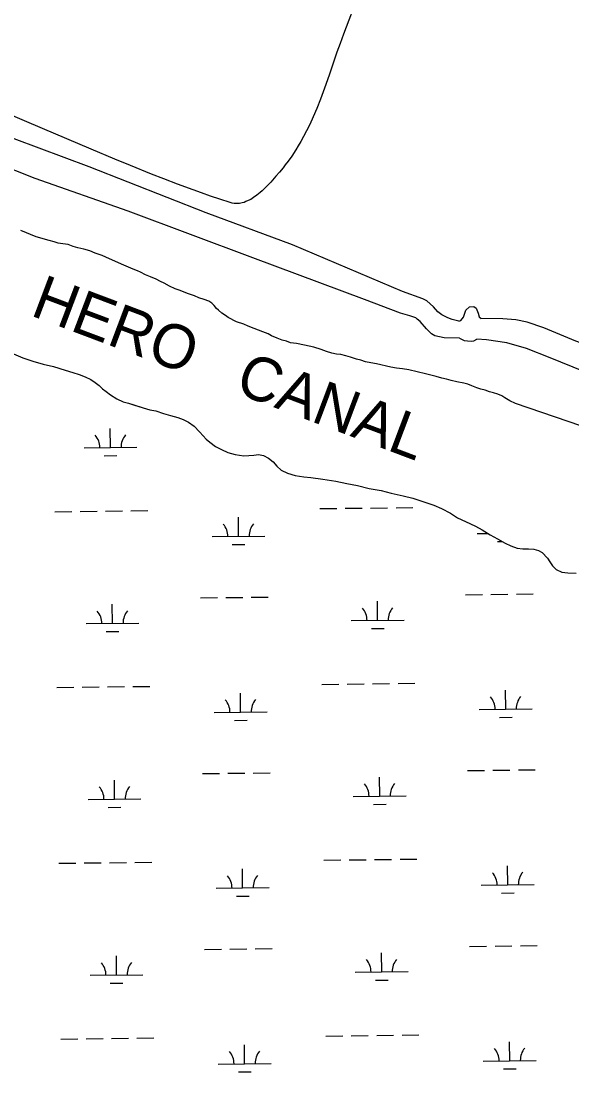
# Model space of a CAD drawing. Extents: x 3678539 to 3716648, y 451386 to 477139.
# Drawn here: x 3688062 to 3689105, y 471723 to 473712 of the extents above; entities that cross this region are included whole.
import ezdxf

# ---------------------------------------------------------------- set-up
doc = ezdxf.new("R2010")
doc.units = 0
for name, color, linetype in [('V-LEVE-TOET', 7, 'Continuous'), ('V-RIVR-IDEN', 7, 'Continuous'), ('V-SITE-VEGE', 7, 'Continuous'), ('V-TOPO-SHOR', 7, 'Continuous'), ('V-WETL-SWMP', 7, 'Continuous')]:
    doc.layers.add(name, color=color, linetype=linetype)

msp = doc.modelspace()

# ---------------------------------------------------------------- linework, layer by layer
at = {"layer": 'V-LEVE-TOET'}
for points in [[(3688890.9, 473144.2), (3688878.2, 473147.4), (3688869.9, 473150.6), (3688858.4, 473156.2), (3688851.3, 473161.8), (3688843, 473171.4), (3688830.4, 473182.9), (3688822.5, 473186.6), (3688784.5, 473200.6), (3688576, 473288.6), (3688412.5, 473349.4), (3688191.3, 473436.2), (3688049.3, 473488.9), (3687970.5, 473514.3), (3687915.5, 473532.1), (3687813.4, 473571.9), (3687684.8, 473628.5), (3687519.9, 473710.3)], [(3687525.9, 473649.2), (3687711, 473557.8), (3687877.2, 473489.1), (3687948.4, 473462.5), (3688011.3, 473445.1), (3688088.5, 473415), (3688264.2, 473352.9), (3688500.5, 473264.8), (3688711.9, 473185.6), (3688779.9, 473160.2), (3688797.7, 473154.6), (3688808.8, 473150.9)], [(3688890.9, 473144.2), (3688894.9, 473145.3), (3688899.4, 473152), (3688904.4, 473165), (3688911.1, 473171.1), (3688919.2, 473172.2), (3688923.9, 473169), (3688927.3, 473159.4), (3688929.6, 473152.1), (3688932.9, 473149.1)], [(3688892.4, 473111.7), (3688863, 473112.7), (3688845.2, 473116.3), (3688839.3, 473120.3), (3688829.4, 473129.9), (3688817.6, 473143.5), (3688811.7, 473148.2), (3688808.8, 473150.9)], [(3690363.1, 472593.4), (3689869.1, 472770.9), (3689805.8, 472791.9), (3689790, 472797.9), (3689781.7, 472803.9), (3689758.3, 472813.5), (3689712.5, 472837.2), (3689691.1, 472844.8), (3689631, 472872.9), (3689518.7, 472942.1), (3689437.7, 472988.5), (3689383.5, 473014.6), (3689375.6, 473017.8), (3689315.8, 473038.8), (3689184.4, 473080.3), (3689112.3, 473106.5), (3689051.8, 473131.8), (3689020.1, 473142.3), (3688998.7, 473146.7), (3688974.2, 473148.9), (3688932.9, 473149.1)], [(3688892.4, 473111.7), (3688901.1, 473107.9), (3688907.2, 473106.7), (3688913.9, 473106.1), (3688919.4, 473107.2), (3688924.9, 473110.4)], [(3691441, 472118), (3691128, 472240.6), (3690885.1, 472340.6), (3690681, 472415.1), (3690462.2, 472494.8), (3690237.1, 472581.2), (3690036.9, 472657.6), (3689882.5, 472713.5), (3689686.7, 472783.2), (3689628.1, 472808.5), (3689612.3, 472817.7), (3689557, 472852.5), (3689499.3, 472888.4), (3689440.1, 472925.6), (3689391, 472951.3), (3689347.9, 472971.3), (3689313.9, 472983.4), (3689191.2, 473023.3), (3689063.8, 473075.1), (3689018.7, 473092.4), (3688981.9, 473103.3), (3688943.5, 473108.7), (3688924.9, 473110.4)]]:
    msp.add_lwpolyline(points, dxfattribs=at)
at = {"layer": 'V-SITE-VEGE'}
msp.add_lwpolyline([(3688700.6, 473762), (3688672.4, 473687.4), (3688666, 473669.7), (3688660.2, 473653.2), (3688645.3, 473609.6), (3688636.8, 473585), (3688629.2, 473564.4), (3688622, 473546.4), (3688615.3, 473530.7), (3688608.8, 473516.5), (3688602.6, 473504.2), (3688596.9, 473493.4), (3688591.6, 473483.9), (3688586.7, 473475.7), (3688582.2, 473468.5), (3688574.4, 473456.7), (3688567.6, 473447.1), (3688562.2, 473439.9), (3688558.1, 473434.5), (3688551.5, 473426.4), (3688544.7, 473418.4), (3688535, 473407.4), (3688526.4, 473398.4), (3688522.4, 473394.5), (3688518.6, 473390.9), (3688515, 473387.7), (3688511.6, 473384.9), (3688508.3, 473382.3), (3688502.4, 473378.1), (3688497, 473374.7), (3688492.2, 473372.2), (3688487.9, 473370.3), (3688484.2, 473368.9), (3688480.9, 473368), (3688478.1, 473367.3), (3688475.5, 473366.9), (3688471.1, 473366.6), (3688467.8, 473366.6), (3688465.3, 473366.8), (3688461.5, 473367.5), (3688457.7, 473368.5), (3688438.5, 473374.8), (3688420.6, 473381), (3688403.7, 473386.9), (3688387.8, 473392.6), (3688358.1, 473403.6), (3688332.1, 473413.6), (3688309.3, 473422.5), (3688269.5, 473438.6), (3688239.7, 473450.9), (3688195.1, 473469.6), (3688103, 473508.8), (3687957, 473570.5)], dxfattribs=at)
at = {"layer": 'V-TOPO-SHOR'}
for points in [[(3688972.3, 473003.1), (3688964.9, 473006.1), (3688956.5, 473008.5), (3688948.8, 473010.7), (3688940.6, 473013.3), (3688932.2, 473015.8), (3688925, 473018.2), (3688915.5, 473021.7), (3688907.6, 473024.9), (3688900.5, 473027.1), (3688887, 473029.5), (3688876.4, 473031.9), (3688867.2, 473034.4), (3688858.5, 473036.5), (3688847.9, 473039.2), (3688837.9, 473041.9), (3688827.8, 473044.4), (3688796.4, 473051.9), (3688784, 473053.9), (3688773.1, 473055.2), (3688762.3, 473057.2), (3688753.9, 473058.8), (3688743.3, 473061.8), (3688734.8, 473063.7), (3688724.3, 473065.6), (3688714, 473067.5), (3688705.2, 473070.2), (3688697.3, 473072.3), (3688685.7, 473075.8), (3688676.7, 473078.5), (3688667.5, 473081.2), (3688659.3, 473082), (3688650.3, 473083.4), (3688640.3, 473086.6), (3688630.2, 473090.4), (3688616.5, 473094.7), (3688598.8, 473099), (3688583.5, 473101.8), (3688572.1, 473103.4), (3688564.7, 473106.1), (3688556.5, 473108.3), (3688546.8, 473112.3), (3688536.5, 473116.3), (3688530.1, 473120), (3688519.6, 473124.3), (3688511.9, 473127), (3688503.5, 473130), (3688492.1, 473134.8), (3688483.7, 473138.5), (3688469.7, 473143.1), (3688454.4, 473150.9), (3688449.4, 473154.6), (3688442.5, 473159.6), (3688436.2, 473164.7), (3688432.3, 473168.4), (3688427.5, 473173.7), (3688423.3, 473178.5), (3688417.8, 473182.3), (3688408.6, 473185.2), (3688398.5, 473188.5), (3688390.3, 473191.9), (3688379, 473196), (3688371.1, 473198.9), (3688363.2, 473201.9), (3688353.9, 473205.6), (3688343.1, 473210.7), (3688333.3, 473215.8), (3688326.2, 473219.3), (3688317.8, 473223.5), (3688307.2, 473228.1), (3688297.7, 473232.1), (3688288, 473237.2), (3688282.7, 473239.3), (3688274.5, 473242.5), (3688265.5, 473246.3), (3688256.8, 473250), (3688229.6, 473262.1), (3688215.7, 473268.5), (3688202.7, 473273.1), (3688192.4, 473277.1), (3688181.1, 473280.3), (3688169.7, 473283), (3688160.5, 473285.7), (3688151.2, 473289.2), (3688141.2, 473290.3), (3688132.2, 473292), (3688124.5, 473294.1), (3688115.3, 473296.8), (3688091, 473303.6), (3688061.4, 473315.6)], [(3688048.1, 473082.1), (3688065.2, 473075.1), (3688084.3, 473068.7), (3688104, 473062.8), (3688123.7, 473058.3), (3688145.5, 473051.3), (3688160.4, 473047), (3688172.2, 473043), (3688183.3, 473039), (3688194.3, 473034), (3688202.7, 473028.1), (3688209.7, 473022.3), (3688216.5, 473016.2), (3688223.1, 473010.9), (3688231.7, 473004.8), (3688243.5, 472996.9), (3688255.6, 472991.8), (3688265.5, 472988.9), (3688275.3, 472985.9), (3688293.4, 472980.1), (3688306, 472976.6), (3688317, 472974.4), (3688331.9, 472969.3)], [(3689247.6, 472903), (3688997.9, 472988.4), (3688987.1, 472993.3), (3688978.1, 472999.4), (3688972.3, 473003.1)], [(3688331.9, 472969.3), (3688344.8, 472965.9), (3688358.7, 472962.1), (3688369.2, 472958.1), (3688379.4, 472953), (3688389.9, 472945.4), (3688400.1, 472934.8), (3688406.6, 472927.4), (3688412.4, 472921.1), (3688419.7, 472915), (3688429.9, 472907.3), (3688441.5, 472901.2), (3688453.5, 472895.9), (3688467.2, 472891.6), (3688484, 472889.4), (3688502.7, 472890.9), (3688511.6, 472891.9), (3688521.3, 472890), (3688530.8, 472885.2), (3688539.1, 472878.3), (3688546.5, 472870.1), (3688554.6, 472862.5), (3688566.4, 472856.4), (3688581.1, 472852.3), (3688597.6, 472849.9), (3688610.7, 472848.5), (3688633.6, 472845.5), (3688658, 472841.4), (3688678.8, 472837.1), (3688698.7, 472833.3), (3688720.8, 472827.7), (3688743.9, 472823.6), (3688762.5, 472818.8), (3688785.4, 472813.9), (3688804, 472809.1), (3688843.4, 472796.2), (3688858.3, 472789.8), (3688874.8, 472781), (3688888.5, 472772.3), (3688903.7, 472765.1), (3688922.3, 472756.1), (3688934.9, 472749.4), (3688950.1, 472740.1), (3688964, 472732.5), (3688978.4, 472724.2), (3688989.1, 472718.9), (3689001.2, 472714.9), (3689012.2, 472713.5), (3689022.5, 472713.5), (3689032.7, 472712.9), (3689041.9, 472710.5), (3689048.7, 472706.2), (3689058.4, 472695.7), (3689062.8, 472688.5), (3689068.3, 472681.4), (3689075.4, 472674.3), (3689085.9, 472669.5), (3689097.2, 472667.9), (3689112.9, 472667.5)]]:
    msp.add_lwpolyline(points, dxfattribs=at)
at = {"layer": 'V-WETL-SWMP'}
for p, q in [((3688048.1, 473082.1), (3688065.2, 473075.1)), ((3688065.2, 473075.1), (3688084.3, 473068.7)), ((3688084.3, 473068.7), (3688104, 473062.8)), ((3688104, 473062.8), (3688123.7, 473058.3)), ((3688123.7, 473058.3), (3688145.5, 473051.3)), ((3688145.5, 473051.3), (3688160.4, 473047)), ((3688160.4, 473047), (3688172.2, 473043)), ((3688172.2, 473043), (3688183.3, 473039)), ((3688183.3, 473039), (3688194.3, 473034)), ((3688194.3, 473034), (3688202.7, 473028.1)), ((3688202.7, 473028.1), (3688209.7, 473022.3)), ((3688209.7, 473022.3), (3688216.5, 473016.2)), ((3688216.5, 473016.2), (3688223.1, 473010.9)), ((3688223.1, 473010.9), (3688231.7, 473004.8)), ((3688231.7, 473004.8), (3688243.5, 472996.9)), ((3688243.5, 472996.9), (3688255.6, 472991.8)), ((3688255.6, 472991.8), (3688265.5, 472988.9)), ((3688265.5, 472988.9), (3688275.2, 472985.9)), ((3688275.2, 472985.9), (3688293.4, 472980.1)), ((3688293.4, 472980.1), (3688306, 472976.6)), ((3688306, 472976.6), (3688317, 472974.4)), ((3688317, 472974.4), (3688331.9, 472969.3)), ((3688331.9, 472969.3), (3688344.8, 472965.9)), ((3688344.8, 472965.9), (3688358.7, 472962.1)), ((3688358.7, 472962.1), (3688369.2, 472958.1)), ((3688369.2, 472958.1), (3688379.4, 472953)), ((3688379.4, 472953), (3688389.9, 472945.4)), ((3688389.9, 472945.4), (3688400.1, 472934.8)), ((3688231.5, 472905), (3688231, 472941)), ((3688400.1, 472934.8), (3688406.6, 472927.4)), ((3688406.6, 472927.4), (3688412.4, 472921.1)), ((3688181.5, 472904.5), (3688281.4, 472905.6)), ((3688412.4, 472921.1), (3688419.7, 472915)), ((3688419.7, 472915), (3688429.9, 472907.3)), ((3688429.9, 472907.3), (3688441.5, 472901.2)), ((3688219.6, 472889.5), (3688243.6, 472889.7)), ((3688441.5, 472901.2), (3688453.5, 472895.9)), ((3688453.5, 472895.9), (3688467.2, 472891.6)), ((3688467.2, 472891.6), (3688484, 472889.4)), ((3688484, 472889.4), (3688502.7, 472890.9)), ((3688502.7, 472890.9), (3688511.6, 472891.9)), ((3688511.6, 472891.9), (3688521.3, 472890)), ((3688521.3, 472890), (3688530.8, 472885.2)), ((3688530.8, 472885.2), (3688539.1, 472878.3)), ((3688539.1, 472878.3), (3688546.4, 472870.1)), ((3688546.4, 472870.1), (3688554.6, 472862.5)), ((3688554.6, 472862.5), (3688566.4, 472856.4)), ((3688566.4, 472856.4), (3688581.1, 472852.3)), ((3688581.1, 472852.3), (3688597.6, 472849.9)), ((3688597.6, 472849.9), (3688610.7, 472848.5)), ((3688610.7, 472848.5), (3688633.6, 472845.5)), ((3688633.6, 472845.5), (3688658, 472841.4)), ((3688658, 472841.4), (3688678.8, 472837.1)), ((3688678.8, 472837.1), (3688698.7, 472833.3)), ((3688698.7, 472833.3), (3688720.8, 472827.7)), ((3688720.8, 472827.7), (3688743.9, 472823.6)), ((3688743.9, 472823.6), (3688762.5, 472818.8)), ((3688762.5, 472818.8), (3688785.4, 472813.9)), ((3688785.4, 472813.9), (3688804, 472809.1)), ((3688804, 472809.1), (3688843.4, 472796.2)), ((3688222, 472784.8), (3688254, 472785.2)), ((3688270, 472785.4), (3688302, 472785.8)), ((3688627.9, 472789.5), (3688659.9, 472789.9)), ((3688675.9, 472790.1), (3688707.9, 472790.4)), ((3688723.9, 472790.6), (3688755.9, 472791)), ((3688771.9, 472791.2), (3688803.9, 472791.5)), ((3688843.4, 472796.2), (3688858.3, 472789.8)), ((3688858.3, 472789.8), (3688874.8, 472781)), ((3688126, 472783.7), (3688158, 472784.1)), ((3688174, 472784.3), (3688206, 472784.7)), ((3688473.9, 472737), (3688473.5, 472773)), ((3688874.8, 472781), (3688888.5, 472772.3)), ((3688888.5, 472772.3), (3688903.7, 472765.1)), ((3688903.7, 472765.1), (3688922.3, 472756.1)), ((3688922.3, 472756.1), (3688934.9, 472749.4)), ((3688934.9, 472749.4), (3688950.1, 472740.1)), ((3688423.9, 472736.4), (3688523.9, 472737.6)), ((3688925.7, 472742.2), (3688946.4, 472742.4)), ((3688950.1, 472740.1), (3688964, 472732.5)), ((3688963.9, 472727.2), (3688973, 472727.3)), ((3688964, 472732.5), (3688978.4, 472724.2)), ((3688462, 472721.4), (3688486, 472721.7)), ((3688978.4, 472724.2), (3688989.1, 472718.9)), ((3688989.1, 472718.9), (3689001.2, 472714.9)), ((3689001.2, 472714.9), (3689012.2, 472713.5)), ((3689012.2, 472713.5), (3689022.5, 472713.5)), ((3689022.5, 472713.5), (3689032.7, 472712.9)), ((3689032.7, 472712.9), (3689041.9, 472710.5)), ((3689041.9, 472710.5), (3689048.7, 472706.2)), ((3689048.7, 472706.2), (3689058.4, 472695.7)), ((3689058.4, 472695.7), (3689062.8, 472688.5)), ((3689062.8, 472688.5), (3689068.3, 472681.4)), ((3689068.3, 472681.4), (3689075.4, 472674.3)), ((3689075.4, 472674.3), (3689085.9, 472669.5)), ((3689085.9, 472669.5), (3689097.2, 472667.9)), ((3689097.2, 472667.9), (3689112.9, 472667.5)), ((3688903.7, 472626.5), (3688935.7, 472626.9)), ((3688951.7, 472627), (3688983.7, 472627.4)), ((3688999.7, 472627.6), (3689031.7, 472628)), ((3688235.3, 472572.4), (3688234.9, 472608.4)), ((3688401.8, 472620.7), (3688433.8, 472621.1)), ((3688449.8, 472621.3), (3688481.8, 472621.6)), ((3688497.8, 472621.8), (3688529.8, 472622.2)), ((3688737.1, 472578.1), (3688736.7, 472614.1)), ((3688185.3, 472571.8), (3688285.3, 472572.9)), ((3688687.2, 472577.6), (3688787.1, 472578.7)), ((3688223.5, 472556.8), (3688247.5, 472557.1)), ((3688725.3, 472562.6), (3688749.3, 472562.8)), ((3688129.8, 472451.1), (3688161.8, 472451.4)), ((3688177.8, 472451.6), (3688209.8, 472452)), ((3688225.8, 472452.2), (3688257.8, 472452.6)), ((3688273.8, 472452.7), (3688305.8, 472453.1)), ((3688631.7, 472456.8), (3688663.7, 472457.2)), ((3688679.7, 472457.4), (3688711.7, 472457.8)), ((3688727.7, 472458), (3688759.7, 472458.3)), ((3688775.7, 472458.5), (3688807.7, 472458.9)), ((3688477.7, 472404.3), (3688477.3, 472440.3)), ((3688979.6, 472410.1), (3688979.2, 472446.1)), ((3688929.6, 472409.5), (3689029.6, 472410.7)), ((3688427.7, 472403.8), (3688527.7, 472404.9)), ((3688465.9, 472388.8), (3688489.9, 472389)), ((3688967.7, 472394.5), (3688991.7, 472394.8)), ((3688405.6, 472288.1), (3688437.6, 472288.4)), ((3688453.6, 472288.6), (3688485.6, 472289)), ((3688501.6, 472289.2), (3688533.6, 472289.5)), ((3688907.5, 472293.8), (3688939.5, 472294.2)), ((3688955.5, 472294.4), (3688987.5, 472294.8)), ((3689003.5, 472294.9), (3689035.5, 472295.3)), ((3688239.1, 472239.7), (3688238.7, 472275.7)), ((3688741, 472245.5), (3688740.6, 472281.5)), ((3688189.1, 472239.1), (3688289.1, 472240.3)), ((3688691, 472244.9), (3688791, 472246.1)), ((3688729.1, 472229.9), (3688753.1, 472230.2)), ((3688227.3, 472224.2), (3688251.3, 472224.4)), ((3688133.6, 472118.4), (3688165.6, 472118.8)), ((3688181.6, 472119), (3688213.6, 472119.3)), ((3688229.6, 472119.5), (3688261.6, 472119.9)), ((3688277.6, 472120.1), (3688309.6, 472120.5)), ((3688635.5, 472124.2), (3688667.5, 472124.6)), ((3688683.5, 472124.7), (3688715.5, 472125.1)), ((3688731.5, 472125.3), (3688763.5, 472125.7)), ((3688779.5, 472125.9), (3688811.5, 472126.2)), ((3688983.4, 472077.4), (3688983, 472113.4)), ((3688481.5, 472071.7), (3688481.1, 472107.7)), ((3688431.5, 472071.1), (3688531.5, 472072.3)), ((3688933.4, 472076.9), (3689033.4, 472078)), ((3688469.7, 472056.1), (3688493.7, 472056.4)), ((3688971.6, 472061.9), (3688995.6, 472062.2)), ((3688409.4, 471955.4), (3688441.4, 471955.8)), ((3688457.4, 471956), (3688489.4, 471956.3)), ((3688505.4, 471956.5), (3688537.4, 471956.9)), ((3688911.3, 471961.2), (3688943.3, 471961.5)), ((3688959.3, 471961.7), (3688991.3, 471962.1)), ((3689007.3, 471962.3), (3689039.3, 471962.7)), ((3688242.9, 471907.1), (3688242.5, 471943.1)), ((3688744.8, 471912.8), (3688744.4, 471948.8)), ((3688694.8, 471912.3), (3688794.8, 471913.4)), ((3688192.9, 471906.5), (3688292.9, 471907.6)), ((3688231.1, 471891.5), (3688255.1, 471891.8)), ((3688733, 471897.3), (3688757, 471897.5)), ((3688639.3, 471791.5), (3688671.3, 471791.9)), ((3688687.3, 471792.1), (3688719.3, 471792.5)), ((3688735.3, 471792.6), (3688767.3, 471793)), ((3688783.3, 471793.2), (3688815.3, 471793.6)), ((3688137.5, 471785.8), (3688169.5, 471786.1)), ((3688185.5, 471786.3), (3688217.5, 471786.7)), ((3688233.5, 471786.9), (3688265.5, 471787.2)), ((3688281.5, 471787.4), (3688313.5, 471787.8)), ((3688485.3, 471739), (3688484.9, 471775)), ((3688987.2, 471744.8), (3688986.8, 471780.8)), ((3688435.3, 471738.5), (3688535.3, 471739.6)), ((3688937.2, 471744.2), (3689037.2, 471745.4)), ((3688473.5, 471723.5), (3688497.5, 471723.7)), ((3688975.4, 471729.2), (3688999.4, 471729.5))]:
    msp.add_line(p, q, dxfattribs=at)
for centre, start, end in [((3688176.2, 472904.9), 359.8865, 41.4302), ((3688286.7, 472906.1), 139.8865, 181.4302), ((3688418.6, 472736.8), 359.8865, 41.4302), ((3688529.1, 472738.1), 139.8865, 181.4302), ((3688180, 472572.2), 359.8865, 41.4302), ((3688290.5, 472573.5), 139.8865, 181.4302), ((3688681.9, 472578), 359.8865, 41.4302), ((3688792.4, 472579.2), 139.8865, 181.4302), ((3688422.4, 472404.2), 359.8865, 41.4302), ((3688532.9, 472405.4), 139.8865, 181.4302), ((3688924.3, 472409.9), 359.8865, 41.4302), ((3689034.8, 472411.2), 139.8865, 181.4302), ((3688685.7, 472245.3), 359.8865, 41.4302), ((3688796.2, 472246.6), 139.8865, 181.4302), ((3688183.9, 472239.6), 359.8865, 41.4302), ((3688294.3, 472240.8), 139.8865, 181.4302), ((3688426.3, 472071.5), 359.8865, 41.4302), ((3688536.7, 472072.8), 139.8865, 181.4302), ((3688928.1, 472077.3), 359.8865, 41.4302), ((3689038.6, 472078.6), 139.8865, 181.4302), ((3688187.7, 471906.9), 359.8865, 41.4302), ((3688298.2, 471908.2), 139.8865, 181.4302), ((3688689.5, 471912.7), 359.8865, 41.4302), ((3688800, 471913.9), 139.8865, 181.4302), ((3688430.1, 471738.9), 359.8865, 41.4302), ((3688540.6, 471740.1), 139.8865, 181.4302), ((3688932, 471744.6), 359.8865, 41.4302), ((3689042.4, 471745.9), 139.8865, 181.4302)]:
    msp.add_arc(centre, 35.2, start, end, dxfattribs=at)

# ---------------------------------------------------------------- texts
at = {"layer": 'V-RIVR-IDEN'}
msp.add_text('HERO   CANAL', height=83, rotation=339.3358, dxfattribs=at).set_placement((3688077.5, 473155.8))

doc.saveas('drawing.dxf')
